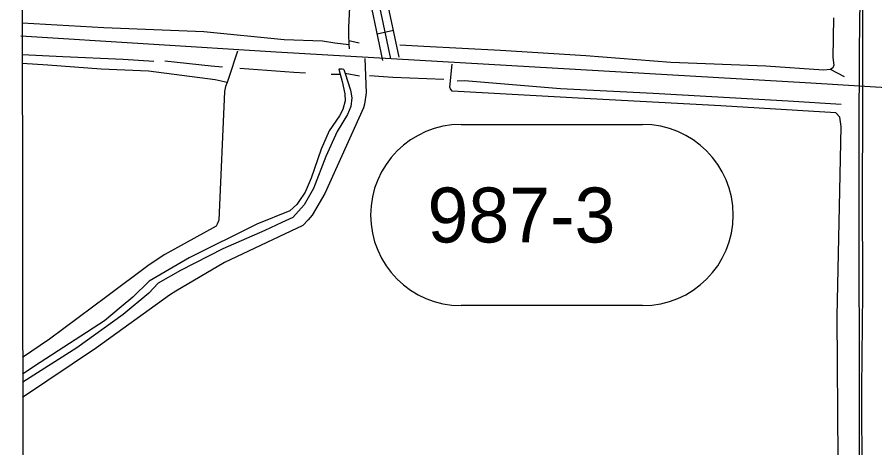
# Model space of a CAD drawing. Extents: x 3313447 to 3351316, y 703786 to 729172.
# Drawn here: x 3317577 to 3319138, y 717443 to 718227 of the extents above; entities that cross this region are included whole.
import ezdxf

# ---------------------------------------------------------------- set-up
doc = ezdxf.new("R2010")
doc.units = 0
for name, color, linetype in [('V-DTCH-CNTR', 7, 'Continuous'), ('V-GRID-FRAM', 7, 'Continuous'), ('V-RAIL-TRAK', 7, 'Continuous'), ('V-ROAD-CNTR', 7, 'Continuous'), ('V-ROAD-IDEN', 7, 'Continuous'), ('V-TOPO-SHOR', 7, 'Continuous')]:
    doc.layers.add(name, color=color, linetype=linetype)

msp = doc.modelspace()

# ---------------------------------------------------------------- linework, layer by layer
at = {"layer": 'V-DTCH-CNTR'}
for points in [[(3317977.8, 718165.2), (3317961.5, 718115.1), (3317958.9, 718108.1), (3317956.1, 718100.6), (3317954.1, 718091.4), (3317943.7, 717857.1), (3317941, 717849.9), (3317939, 717846.6), (3317845.5, 717794.5), (3317816.9, 717775.6), (3317739.9, 717718.1), (3317635.6, 717640.3), (3317586.8, 717607)], [(3318209.9, 718151.9), (3318212.1, 718089.2), (3318209.3, 718068.7), (3318207.3, 718061.5), (3318136.7, 717905.6), (3318114, 717866.1), (3318106.6, 717857.6), (3318096.6, 717847.8), (3317954.2, 717780.2), (3317866, 717728.1), (3317854, 717720.9), (3317721.2, 717624.9), (3317586.9, 717534.5)], [(3317958.9, 718108.1), (3317937.2, 718112.9), (3317815.8, 718128.4), (3317730, 718132.4), (3317633, 718139.7), (3317586.3, 718142.4)], [(3319066.9, 718052.4), (3318857.7, 718065.2), (3318598.3, 718079.1), (3318368.6, 718092.1), (3318365.4, 718096.1), (3318364.7, 718099.4), (3318368.4, 718141.5)], [(3317587.1, 717331.7), (3317726.1, 717323.6), (3317959.8, 717308.6), (3318139.3, 717298.6), (3318328.6, 717282), (3318556.3, 717267), (3318772.1, 717256), (3318984, 717246.5), (3319064.4, 717239.9), (3319072.4, 717239.2), (3319073.1, 717244.4), (3319071.1, 717421.4), (3319069.2, 717682.2), (3319074.3, 717910.6), (3319076.6, 718028.1), (3319074, 718044.6), (3319066.9, 718052.4)]]:
    msp.add_lwpolyline(points, dxfattribs=at)
at = {"layer": 'V-GRID-FRAM'}
msp.add_lwpolyline([(3317576.9, 727351), (3317595.4, 709166), (3349105.8, 709211.8), (3349071.4, 727396.8), (3317576.9, 727351)], dxfattribs=at)
at = {"layer": 'V-RAIL-TRAK'}
msp.add_lwpolyline([(3319121.8, 719295.6), (3319119.3, 719204.7), (3319120.5, 719016.3), (3319117.5, 718744.7), (3319116.3, 718534.2), (3319115.8, 718298.8), (3319115.8, 718122.7), (3319115.7, 718094.5), (3319115.7, 718047.1), (3319115, 717911.7), (3319115.4, 717725.7), (3319114, 717550.5), (3319114.5, 717379.8)], dxfattribs=at)
at = {"layer": 'V-ROAD-CNTR'}
msp.add_line((3318232.4, 718196.8), (3318261.7, 718203), dxfattribs=at)
for points in [[(3319123.3, 722052), (3319125.5, 721671.5), (3319128.2, 721217.9), (3319125.1, 720896.4), (3319122.9, 720619.8), (3319119.4, 720058.8), (3319120.2, 719571), (3319117.5, 719133), (3319116.3, 718677.5), (3319109.6, 718166.1), (3319108.6, 718011.2), (3319109.7, 717385.5), (3319107.1, 716859), (3319102.5, 716067.5), (3319104.4, 715556.2)], [(3318272, 718154), (3318241.4, 718299.8), (3318241.4, 718323.3), (3318250.1, 718347), (3318264.9, 718379.9), (3318273.8, 718415.6), (3318283.5, 718459)], [(3318242.7, 718147.9), (3318211.4, 718296.7), (3318211.4, 718314.2)], [(3318257.3, 718151), (3318226.4, 718298.2)], [(3320627.7, 718008.6), (3320049.5, 718044.1), (3319581.5, 718072.4), (3319021.7, 718106.6), (3318048.4, 718163.1), (3317583.9, 718192.4)]]:
    msp.add_lwpolyline(points, dxfattribs=at)
at = {"layer": 'V-ROAD-IDEN'}
for p, q in [((3318385.2, 718031.6), (3318715.2, 718031.6)), ((3318715.2, 717701.6), (3318385.2, 717701.6))]:
    msp.add_line(p, q, dxfattribs=at)
for centre, start, end in [((3318385.2, 717866.6), 90, 270), ((3318715.2, 717866.6), 270, 90)]:
    msp.add_arc(centre, 165, start, end, dxfattribs=at)
at = {"layer": 'V-TOPO-SHOR'}
for p, q in [((3318199.3, 718179.4), (3318180.3, 718184.1)), ((3319082.5, 718118.1), (3319057.1, 718131.3)), ((3318148.6, 718122.8), (3318164.7, 718123.2)), ((3318200.2, 718119.7), (3318174, 718124.1))]:
    msp.add_line(p, q, dxfattribs=at)
for points in [[(3318190, 718309.8), (3318184, 718274.1), (3318181.8, 718245.3), (3318180.1, 718208.3), (3318180, 718188.8), (3318180.3, 718184.1), (3318180.9, 718177), (3318181.5, 718169.1)], [(3319062.5, 718225.6), (3319061.3, 718153.5), (3319063.2, 718139.3), (3319061.8, 718134.6), (3319057.1, 718131.3), (3319044.3, 718130.1), (3318939.6, 718137.6), (3318766.9, 718144.3), (3318611.7, 718156.3), (3318456.6, 718166.2), (3318316.9, 718173.4), (3318273.7, 718176.1)], [(3317586.2, 718216.6), (3317734.8, 718207.9), (3317916.8, 718201.1), (3318062.6, 718186.5), (3318132.4, 718184), (3318155.3, 718180.4), (3318180.9, 718177)], [(3317586.3, 718159), (3317660.2, 718155.4), (3317769.7, 718150.5), (3317825.6, 718146.8)], [(3317845.8, 718147.3), (3317930.3, 718138.5), (3317950.9, 718136.4)], [(3318171.5, 718131.8), (3318168.5, 718132.3), (3318162.1, 718132.5), (3318164.7, 718123.2), (3318168.6, 718109.6), (3318173.1, 718087.4), (3318173.7, 718074.6), (3318169.5, 718058.5), (3318163.4, 718047.2), (3318145.1, 718019.7), (3318130, 717986.3), (3318112.1, 717934), (3318101.2, 717908.5), (3318089.6, 717891.2), (3318086.2, 717885.8), (3318073.4, 717874.5), (3318013.3, 717850.1), (3317889.9, 717788.5), (3317817, 717746.1), (3317787.2, 717716.8), (3317766.2, 717699.5), (3317735.8, 717674.2), (3317618.9, 717597.8), (3317586.9, 717576.8)], [(3318171.5, 718131.8), (3318174, 718124.1), (3318183.9, 718094), (3318185.8, 718079.9), (3318184.4, 718064.5), (3318178.2, 718049.7), (3318159.2, 718019), (3318138.6, 717973.4), (3318116, 717915.1), (3318099.6, 717885), (3318078.6, 717862.3), (3318058.4, 717853.1), (3318028, 717838.5), (3317951.2, 717804.9), (3317874.3, 717765.8), (3317833.7, 717742.6), (3317816.8, 717724.6), (3317770.1, 717685.3), (3317685.7, 717624.8), (3317587, 717562.4), (3317586.9, 717562.3)], [(3317982.4, 718134.1), (3318080.7, 718126.6), (3318101.7, 718125.8)], [(3318353.7, 718113.1), (3318260.7, 718117), (3318218.3, 718120.2)], [(3319076.9, 718067.6), (3318980.1, 718073.7), (3318734.3, 718087.7), (3318565.7, 718096.4), (3318391.1, 718111.2), (3318377.8, 718110.3)]]:
    msp.add_lwpolyline(points, dxfattribs=at)

# ---------------------------------------------------------------- texts
at = {"layer": 'V-ROAD-IDEN'}
msp.add_text('987-3', height=100, dxfattribs=at).set_placement((3318323.8, 717816.6))

doc.saveas('drawing.dxf')
